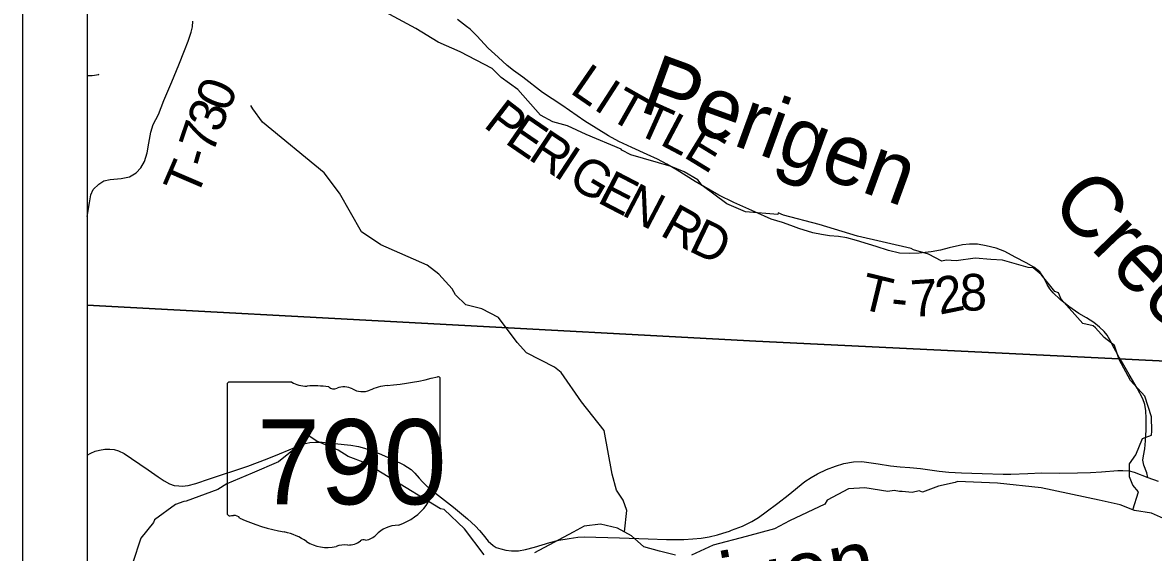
# Model space of a CAD drawing. Extents: x -1.8 to 75.7, y -2 to 25.
# Drawn here: x 2 to 3.751, y 16.983 to 17.804 of the extents above; entities that cross this region are included whole.
import ezdxf

# ---------------------------------------------------------------- set-up
doc = ezdxf.new("R2010")
doc.units = 0
for name, color, linetype in [('GM_X_Minor_River', 7, 'Continuous'), ('GM_X_Minor_River_Text', 7, 'Continuous'), ('GM_X_State_Location', 7, 'Continuous'), ('GM_X_State_Route', 7, 'Continuous'), ('GM_X_State_Shield', 7, 'Continuous'), ('GM_X_Township', 7, 'Continuous'), ('GM_X_Township_Road', 7, 'Continuous'), ('GM_X_Township_Road_Text', 7, 'Continuous'), ('SH_Data', 7, 'Continuous')]:
    doc.layers.add(name, color=color, linetype=linetype)

msp = doc.modelspace()

# ---------------------------------------------------------------- linework, layer by layer
at = {"layer": 'GM_X_Minor_River'}
for points in [[(3.719, 17.0489), (3.7276, 17.0768), (3.7189, 17.087), (3.7136, 17.0999), (3.714, 17.1201), (3.7238, 17.1342), (3.734, 17.1593), (3.748, 17.1643), (3.7483, 17.1707), (3.7479, 17.1928), (3.7373, 17.2247), (3.7154, 17.2493), (3.698, 17.2816), (3.6908, 17.3036), (3.6745, 17.3157), (3.6612, 17.3305), (3.6575, 17.3336), (3.6416, 17.3377), (3.6079, 17.3752), (3.6037, 17.3851), (3.5984, 17.387), (3.5772, 17.4136), (3.5644, 17.4238), (3.5568, 17.4242), (3.5171, 17.4355), (3.4993, 17.4366), (3.4748, 17.4388), (3.4453, 17.4345), (3.4298, 17.4356), (3.423, 17.4341), (3.4026, 17.4451), (3.3795, 17.4515), (3.3757, 17.4534), (3.2929, 17.4729), (3.2335, 17.491), (3.1783, 17.5053), (3.17, 17.5087), (3.1693, 17.5064), (3.119, 17.5105), (3.0902, 17.5226), (3.052, 17.5514), (3.0452, 17.5601), (3.0244, 17.5726), (3.004, 17.5805), (2.9416, 17.599), (2.928, 17.6058), (2.9265, 17.6077), (2.8728, 17.6304), (2.8437, 17.6436), (2.821, 17.6497), (2.8017, 17.6603), (2.7665, 17.7001), (2.7411, 17.7186), (2.7268, 17.7323), (2.6776, 17.7584), (2.6436, 17.7731), (2.6088, 17.7943), (2.5274, 17.8382)], [(2.1, 17.7214), (2.1076, 17.7217), (2.1178, 17.7232), (2.117, 17.7228)], [(2.9321, 17.0146), (2.9355, 17.0477), (2.9299, 17.0639), (2.9194, 17.0794), (2.9126, 17.1039), (2.9003, 17.1715), (2.8653, 17.2159), (2.8338, 17.2617), (2.8235, 17.27), (2.7803, 17.2919), (2.7657, 17.308), (2.737, 17.3468), (2.711, 17.3602), (2.6862, 17.3663), (2.67, 17.382), (2.665, 17.3909), (2.6442, 17.414), (2.6264, 17.4278), (2.5548, 17.4594), (2.5245, 17.4797), (2.4904, 17.5396), (2.4667, 17.5708), (2.3716, 17.6494), (2.3563, 17.67), (2.3531, 17.675)], [(2.7147, 16.9792), (2.6844, 17.0191), (2.6526, 17.0494), (2.6469, 17.0505), (2.566, 17.0997), (2.5312, 17.1209), (2.5043, 17.1315), (2.4888, 17.1414), (2.4555, 17.155), (2.4423, 17.1641), (2.4381, 17.166), (2.4287, 17.1496), (2.4121, 17.1359), (2.3962, 17.1233), (2.3554, 17.1057), (2.3161, 17.0893), (2.3025, 17.0801), (2.2534, 17.0621), (2.2496, 17.0617), (2.2368, 17.0571), (2.2043, 17.0335), (2.2024, 17.0289), (2.1831, 17.0049), (2.17, 16.9657)], [(3.4476, 17.0925), (3.4441, 17.0909), (3.418, 17.0855), (3.3931, 17.076), (3.3882, 17.0782), (3.3772, 17.0755), (3.3617, 17.077), (3.3579, 17.077), (3.3496, 17.0789), (3.3398, 17.077), (3.3039, 17.0826), (3.2789, 17.0814), (3.2457, 17.0638), (3.2423, 17.0577), (3.1875, 17.0317), (3.1641, 17.0195), (3.1202, 17.0076), (3.0692, 16.9938), (3.0356, 16.9785)], [(4.0627, 16.9472), (3.9889, 16.9912), (3.9681, 17.0014), (3.9243, 17.0339), (3.905, 17.0423), (3.877, 17.0467), (3.8494, 17.0402), (3.8456, 17.0387), (3.8033, 17.0279), (3.7712, 17.0332), (3.7481, 17.0434), (3.7216, 17.0479), (3.6993, 17.0566), (3.6668, 17.0637), (3.5772, 17.0829), (3.5095, 17.0899), (3.4476, 17.0925)], [(3.011, 16.9785), (2.9861, 16.9849), (2.9619, 16.9916), (2.9426, 17.0087), (2.921, 17.0204), (2.8949, 17.0264), (2.8692, 17.0237), (2.8526, 17.0142), (2.7925, 16.9821)]]:
    msp.add_lwpolyline(points, dxfattribs=at)
at = {"layer": 'GM_X_State_Route'}
for points in [[(2.1, 17.1333), (2.1056, 17.1365), (2.1121, 17.1395), (2.1192, 17.1413), (2.1273, 17.1427), (2.135, 17.1427), (2.1419, 17.1423), (2.1484, 17.1403), (2.1573, 17.1361), (2.1686, 17.1284), (2.1945, 17.1105), (2.2099, 17.1), (2.2191, 17.0935), (2.2276, 17.0891), (2.2347, 17.0866), (2.242, 17.0858), (2.2468, 17.0856), (2.2564, 17.0866), (2.2681, 17.0897), (2.2896, 17.0966), (2.3486, 17.1166), (2.3787, 17.1278), (2.3976, 17.1355), (2.4276, 17.1478), (2.4355, 17.1511), (2.4448, 17.1531), (2.4537, 17.1535), (2.4636, 17.1535), (2.4827, 17.1517), (2.5082, 17.1488), (2.52, 17.1468), (2.5293, 17.1444), (2.5518, 17.1359), (2.5741, 17.1261), (2.5901, 17.1184), (2.596, 17.115), (2.6018, 17.1111), (2.6073, 17.1055), (2.6138, 17.0978), (2.6191, 17.0921), (2.6255, 17.0858), (2.6312, 17.0807), (2.6365, 17.0765), (2.644, 17.0708), (2.6669, 17.0528), (2.6886, 17.0347), (2.7013, 17.0236), (2.7076, 17.0167), (2.7129, 17.0102), (2.7206, 17.0003), (2.7283, 16.9936), (2.7334, 16.9906), (2.7404, 16.9883), (2.7483, 16.9861), (2.7571, 16.9853), (2.7676, 16.9853), (2.7785, 16.9871), (2.7923, 16.991), (2.7925, 16.9911)], [(3.0978, 17.0172), (3.1147, 17.0234), (3.1289, 17.0305), (3.1392, 17.037), (3.1512, 17.0455), (3.1694, 17.0593), (3.1852, 17.0714), (3.2112, 17.0925), (3.2207, 17.0988), (3.2308, 17.1047), (3.2444, 17.1113), (3.2588, 17.1166), (3.2717, 17.1203), (3.2863, 17.1231), (3.2995, 17.1235), (3.3246, 17.1201), (3.3439, 17.117), (3.3585, 17.1154), (3.3737, 17.1142), (3.3901, 17.1128), (3.4191, 17.1089), (3.4343, 17.1073), (3.4539, 17.1063), (3.4857, 17.105), (3.5182, 17.1038), (3.5301, 17.1038), (3.5564, 17.1053), (3.5775, 17.1059), (3.6055, 17.1057), (3.6334, 17.1061), (3.6533, 17.1065), (3.6705, 17.1075), (3.6959, 17.1095), (3.7034, 17.1099), (3.7133, 17.1091), (3.721, 17.1073), (3.7421, 17.099), (3.7581, 17.0933)], [(2.7925, 16.9911), (2.8162, 16.9983), (2.8302, 17.0017), (2.8464, 17.0046), (2.8598, 17.0064), (2.8697, 17.007), (2.9242, 17.0054), (2.9542, 17.0043), (2.9686, 17.0039), (2.997, 17.0029), (3.0239, 17.0027), (3.0379, 17.0037), (3.0505, 17.005), (3.063, 17.007), (3.076, 17.0102), (3.0843, 17.0127), (3.0944, 17.0159), (3.0978, 17.0172)]]:
    msp.add_lwpolyline(points, dxfattribs=at)
at = {"layer": 'GM_X_State_Shield'}
for p, q in [((2.4166, 17.2467), (2.3201, 17.2467)), ((2.6464, 17.147), (2.6464, 17.2517)), ((2.3168, 17.2433), (2.3168, 17.0431)), ((2.6464, 17.147), (2.6464, 17.147))]:
    msp.add_line(p, q, dxfattribs=at)
for centre, major_axis, start_param, end_param in [((2.3206, 17.2437), (0.00382, 0), 1.712693, 3.28349), ((2.4396, 17.2699), (0.037, 0), 4.042523, 4.731795), ((2.529, 17.5195), (0.3495, 0), 4.814394, 5.042369), ((2.6428, 17.2521), (0.00367, 0), 6.141152, 7.989035), ((2.4519, 17.1344), (0.133, 0), 1.404758, 1.657858), ((2.4821, 17.2447), (0.0107, 0), 3.836095, 5.185415), ((2.4977, 17.2216), (0.0222, 0), 0.950623, 2.079405), ((2.5264, 17.2533), (0.0267, 0), 4.081561, 5.145723), ((2.5736, 17.1856), (0.0703, 0), 1.699011, 2.107814), ((2.6456, 17.1393), (0.00568, 0), 1.883978, 3.671073), ((2.6425, 17.1466), (0.00393, 0), 5.05454, 6.418171), ((2.6095, 17.1261), (0.0341, 0), 5.934695, 6.695948), ((2.6596, 17.1032), (0.0248, 0), 2.387724, 3.262537), ((2.5486, 17.0899), (0.0874, 0), 5.101752, 6.440018), ((2.3207, 17.0427), (0.00385, 0), 3.00124, 4.508301), ((2.3212, 17.0632), (0.0294, 0), 4.665946, 4.897461), ((2.3273, 17.0316), (0.0106, 0), 0.519207, 1.627899), ((2.4611, 17.2114), (0.2524, 0), 4.195997, 4.488961), ((2.5855, 16.987), (0.0479, 0), 1.647645, 2.488434), ((2.3858, 16.9532), (0.079, 0), 0.823519, 1.323587), ((2.5039, 17.0156), (0.0267, 0), 4.691044, 5.507374), ((2.528, 16.9962), (0.00752, 0), 1.147584, 2.315152), ((2.5248, 17.0237), (0.0282, 0), 4.937069, 5.64225), ((2.4712, 17.0306), (0.0501, 0), 4.026481, 4.996735), ((2.5002, 16.9614), (0.0412, 0), 1.495662, 1.94098)]:
    msp.add_ellipse(centre, major_axis=major_axis, ratio=0.8, start_param=start_param, end_param=end_param, dxfattribs=at)
at = {"layer": 'GM_X_Township'}
for points in [[(6.4874, 20.9), (2.1, 20.9), (2.1, 17.3659)], [(2.1, 17.3659), (3.1354, 17.3103), (3.6863, 17.2831), (4.4195, 17.2469), (4.6712, 17.2345), (5.2191, 17.2074), (5.4813, 17.1939), (6.252, 17.1543), (6.3199, 17.9861), (6.3212, 18.0078), (6.3226, 18.0577), (6.3233, 18.0805), (6.3259, 18.1065), (6.3299, 18.1515), (6.3889, 19.1678), (6.4185, 19.6642), (6.4493, 20.1816), (6.4874, 20.9)], [(2.1, 17.3659), (2.1, 14.1), (6.0631, 14.1)], [(6.0631, 14.1), (6.0891, 14.525), (6.1136, 14.9242), (6.1259, 15.1242), (6.1707, 15.8638), (6.1898, 16.179), (6.2265, 16.7539), (6.252, 17.1543), (5.4813, 17.1939), (5.2191, 17.2074), (4.6712, 17.2345), (4.4195, 17.2469), (3.6863, 17.2831), (3.1354, 17.3103), (2.1, 17.3659)]]:
    msp.add_lwpolyline(points, dxfattribs=at)
at = {"layer": 'GM_X_Township_Road'}
for points in [[(2.1, 17.503), (2.1035, 17.5242), (2.1055, 17.5366), (2.1093, 17.5451), (2.1178, 17.5534), (2.1259, 17.5583), (2.1353, 17.5603), (2.1528, 17.5619), (2.1654, 17.5646), (2.1756, 17.5706), (2.183, 17.5785), (2.1889, 17.5886), (2.1929, 17.6016), (2.1954, 17.6166), (2.1985, 17.6341), (2.2023, 17.6455), (2.2102, 17.661), (2.2187, 17.6831), (2.231, 17.712), (2.2418, 17.7383), (2.2507, 17.7602), (2.2563, 17.7748), (2.2608, 17.7889), (2.2628, 17.797), (2.2635, 17.806)], [(3.697, 17.2864), (3.695, 17.2899), (3.69, 17.2994), (3.6835, 17.3121), (3.6792, 17.3194), (3.6746, 17.3251), (3.6671, 17.332), (3.6584, 17.3391), (3.647, 17.3462), (3.6355, 17.3529), (3.6201, 17.3636), (3.6063, 17.3748), (3.5954, 17.3851), (3.5905, 17.3914), (3.5864, 17.3981), (3.5808, 17.409), (3.5747, 17.4173), (3.5656, 17.4246), (3.5536, 17.4313), (3.5368, 17.44), (3.5206, 17.4489), (3.5072, 17.4542), (3.4918, 17.458), (3.4784, 17.4603), (3.4659, 17.4603), (3.4551, 17.4591), (3.4345, 17.4548), (3.4211, 17.4512), (3.4069, 17.4485), (3.3883, 17.4465), (3.3739, 17.4461), (3.3575, 17.4465), (3.3406, 17.4505), (3.3214, 17.4566), (3.3098, 17.4601), (3.2912, 17.466), (3.276, 17.47), (3.2634, 17.472), (3.2495, 17.4732), (3.2369, 17.4751), (3.2233, 17.4781), (3.2018, 17.4844), (3.1895, 17.4895), (3.1767, 17.4937), (3.1589, 17.4992), (3.1336, 17.5103), (3.1011, 17.5247), (3.0782, 17.5361), (3.0412, 17.5573), (3.0134, 17.5748), (2.9974, 17.5841), (2.9832, 17.592), (2.9672, 17.5995), (2.9433, 17.6102), (2.923, 17.6195), (2.907, 17.6281), (2.8882, 17.6398), (2.8707, 17.6508), (2.8347, 17.6755), (2.8047, 17.6955), (2.7745, 17.719), (2.7599, 17.7296), (2.75, 17.7373), (2.7364, 17.7502), (2.7208, 17.7642), (2.7032, 17.7833), (2.6928, 17.7932), (2.6871, 17.7975), (2.6734, 17.8086)], [(3.7421, 17.099), (3.7406, 17.1063), (3.7358, 17.118), (3.7346, 17.1259), (3.7354, 17.1322), (3.7376, 17.1432), (3.7388, 17.1557), (3.7398, 17.1725), (3.7398, 17.1908), (3.7392, 17.2021), (3.7374, 17.2118), (3.7344, 17.2208), (3.7258, 17.2372), (3.7133, 17.2582), (3.7027, 17.2767), (3.6993, 17.2825), (3.697, 17.2864)]]:
    msp.add_lwpolyline(points, dxfattribs=at)
at = {"layer": 'SH_Data'}
for p, q in [((2, 21), (2, 14)), ((2.1, 20.9), (2.1, 14.1))]:
    msp.add_line(p, q, dxfattribs=at)

# ---------------------------------------------------------------- texts
at = {"layer": 'GM_X_Minor_River_Text'}
for s, height, rotation, p in [('Perigen', 0.09469, 340.0029, (2.9522, 17.6675)), ('Creek', 0.0947, 314.0019, (3.5886, 17.5197)), ('Perigen', 0.0947, 10.0083, (2.8957, 16.8515))]:
    msp.add_text(s, height=height, rotation=rotation, dxfattribs=at).set_placement(p)
at = {"layer": 'GM_X_State_Location'}
for s in ['s', 'r']:
    msp.add_text(s, height=0.000189, dxfattribs=at).set_placement((2.4779, 17.1299))
msp.add_text('790', height=0.000189, rotation=0, dxfattribs=at).set_placement((2.4111, 17.1161))
at = {"layer": 'GM_X_State_Shield'}
msp.add_text('790', height=0.13184, dxfattribs=at).set_placement((2.3624, 17.0573))
at = {"layer": 'GM_X_Township_Road_Text'}
for s, rotation, p in [('L', 325.4107, (2.8456, 17.6958)), ('0', 67.5356, (2.3181, 17.6631)), ('I', 327.159, (2.8821, 17.6706)), ('T', 330.5158, (2.9047, 17.6561)), ('3', 68.5958, (2.3055, 17.6308)), ('P', 322.463, (2.7117, 17.6432)), ('T', 335.7988, (2.9468, 17.6327)), ('7', 71.2343, (2.2944, 17.5983)), ('E', 325.5485, (2.7448, 17.6179)), ('L', 332.1047, (2.9847, 17.6157)), ('R', 326.635, (2.7808, 17.5932)), ('E', 328.4839, (3.0214, 17.5963)), ('-', 73.8409, (2.2881, 17.5766)), ('I', 326.7269, (2.8199, 17.5675)), ('T', 66.7015, (2.2687, 17.5303)), ('G', 329.3578, (2.8418, 17.5532)), ('E', 332.4783, (2.8878, 17.5261)), ('N', 332.4428, (2.9255, 17.5064)), ('R', 330.8612, (2.9849, 17.4753)), ('D', 334.4086, (3.0291, 17.4508)), ('T', 346.3411, (3.2933, 17.3613)), ('7', 3.9594, (3.3767, 17.3473)), ('2', 11.512, (3.4197, 17.3509)), ('8', 359.9349, (3.451, 17.3575)), ('-', 354.1829, (3.3429, 17.3499))]:
    msp.add_text(s, height=0.0568, rotation=rotation, dxfattribs=at).set_placement(p)

doc.saveas('drawing.dxf')
